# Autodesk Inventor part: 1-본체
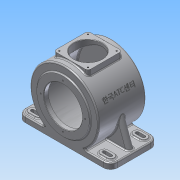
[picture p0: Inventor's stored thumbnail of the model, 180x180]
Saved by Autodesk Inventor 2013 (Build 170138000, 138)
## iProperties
Created: 2015-06
Part Number: 1-본체
Material: 알루미늄 6061
Document SubType Name: Modeling
Designer: ST5
Density: 2.71 g/cm^3
Mass: 3341.58 g
Surface Area: 2297.32 cm^2
Volume: 1233.06 cm^3
Author: ST5
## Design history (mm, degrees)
sketch "스케치1"
  geometry: L1 (-115, 59)-(115, 59); L2 (115, 59)-(115, -59); L3 (115, -59)-(-115, -59); L4 (-115, -59)-(-115, 59); 3 further points
  constraints: 8 end point, 2 midpoint, 2 parallel, 1 horizontal, 1 horizontal alignment, 1 perpendicular, 1 vertical alignment
  dimensions: "d0" = 230 distance of L1.start L1.end; "d2" = 118 distance of L3.end L1.start
extrude "돌출1" new body sketch "스케치1" distance "d3" = 14; taper "d4" = 0 deg
node "작업 평면1"
sketch "스케치2"
  geometry: L1 (115, 0)-(-115, 0) reference; C1 r 85 at (0, 85); 2 further points
  constraints: 1 centre point, 1 midpoint, 1 vertical alignment
  dimensions: "d6" = 170 diameter of C1; "d8" = 85 distance of point (0, 0) C1.centre
extrude "돌출2" join sketch "스케치2" stored distance "d9" = 118; taper "d10" = 0 deg
node "작업 평면2"
sketch "스케치3"
  geometry: L1 (-42.5, 42.5)-(42.5, 42.5); L2 (42.5, 42.5)-(42.5, -42.5); L3 (42.5, -42.5)-(-42.5, -42.5); L4 (-42.5, -42.5)-(-42.5, 42.5); 3 further points
  constraints: 8 end point, 2 midpoint, 2 parallel, 2 perpendicular, 1 horizontal, 1 horizontal alignment, 1 vertical alignment
  dimensions: "d12" = 85 distance of L1.start L1.end
extrude "돌출3" join sketch "스케치3" stored distance "d14" = 118; taper "d15" = 0 deg
node "작업 평면3"
sketch "스케치4"
  geometry: L1 (0, 14)-(68.267, 14) reference; L2 (0, 0)-(0, 14) reference; L3 (230, 0)-(0, 0) reference; L4 (230, 0)-(230, 14) reference; L5 (161.733, 14)-(230, 14) reference; L6 (6, 14)-(30.13, 80.297); L7 (0, 14)-(68.267, 14) reference; A1 r 85 centre (115, 85) between (161.733, 14) and (68.267, 14) reference; 1 further point
  constraints: 2 end point, 1 point on circle, 1 point on line
  dimensions: "d16" = 6 distance from line of L2 L6.start; "d17" = 110 deg angle of L1 L6
extrude "돌출4" join sketch "스케치4" stored distance "d18" = 15; taper "d19" = 0 deg
node "작업 평면4"
sketch "스케치5"
  geometry: C1 r 65 at (115, 85); A1 r 85 centre (115, 85) between (161.733, 14) and (68.267, 14) reference; 1 further point
  constraints: 1 centre point, 1 coincident
  dimensions: "d21" = 130 diameter of C1
extrude "돌출5" join sketch "스케치5" distance "d23" = 3; taper "d24" = 0 deg
sketch "스케치6"
  geometry: C1 r 65 at (0, 0) reference; C2 r 47.5 at (0, 0); 1 further point
  constraints: 1 centre point, 1 coincident
  dimensions: "d25" = 95 diameter of C2
extrude "돌출6" cut sketch "스케치6" distance "d27" = 11; taper "d28" = 0 deg
sketch "스케치7"
  geometry: C1 r 47.5 at (0, 0) reference; C2 r 77 at (0, 0); 1 further point
  constraints: 1 centre point, 1 coincident
  dimensions: "d29" = 154 diameter of C2
extrude "돌출7" cut sketch "스케치7" distance "d31" = 102; taper "d32" = 0 deg
sketch "스케치8"
  geometry: C1 r 77 at (0, 0) reference; C2 r 31 at (0, 0); 1 further point
  constraints: 1 centre point, 1 coincident
  dimensions: "d33" = 62 diameter of C2
extrude "돌출8" join sketch "스케치8" distance "d35" = 3.5; taper "d36" = -25 deg
sketch "스케치9"
  geometry: C1 r 65 at (115, -85); A1 r 85 centre (115, -85) between (68.267, -14) and (161.733, -14) reference; 1 further point
  constraints: 1 centre point, 1 coincident
  dimensions: "d37" = 130 diameter of C1
extrude "돌출9" join sketch "스케치9" distance "d39" = 13; taper "d40" = 0 deg
sketch "스케치10"
  geometry: C1 r 29.368 at (0, 0) reference; C2 r 23.5 at (0, 0); 1 further point
  constraints: 1 centre point, 1 coincident
  dimensions: "d41" = 47 diameter of C2
extrude "돌출10" cut sketch "스케치10" distance "d43" = 14; taper "d44" = 0 deg
sketch "스케치11"
  geometry: C1 r 23.5 at (0, 0) reference; C2 r 15 at (0, 0); 1 further point
  constraints: 1 centre point, 1 coincident
  dimensions: "d45" = 30 diameter of C2
extrude "돌출11" cut sketch "스케치11" distance "d47" = 3; taper "d48" = 0 deg
fillet "모깎기1" dims "d49" = 0.3
fillet "모깎기2" dims "d50" = 3
chamfer "모따기1" distance "d51" = 1; stored, may be unused: second distance "d52" = 2, angle "d53" = 45 deg
fillet "모깎기4" dims "d55" = 3
fillet "모깎기5" dims "d56" = 3
fillet "모깎기6" dims "d57" = 3
fillet "모깎기7" dims "d58" = 7.5
fillet "모깎기8" dims "d59" = 7
fillet "모깎기9" dims "d60" = 18
sketch "스케치12"
  geometry: C1 r 65 at (0, 0) reference; 2 further points
  constraints: 1 vertical alignment
  dimensions: "d61" = 55 distance of C1.centre point (0, 55)
hole "구멍1" sketch "스케치12" at (0, 55) diameter "d62" = 3.459; stored, may be unused: countersink angle "d66" = 90 deg, drill point angle "d68" = 118 deg; dims "d63" = 20, "d64" = 4, "d65" = 2, "d67" = 20
sketch "스케치13"
  geometry: A1 r 7 centre (-35.5, 35.5) between (-35.5, 42.5) and (-42.5, 35.5) reference; A2 r 7 centre (-35.5, -35.5) between (-42.5, -35.5) and (-35.5, -42.5) reference; A3 r 7 centre (35.5, -35.5) between (35.5, -42.5) and (42.5, -35.5) reference; A4 r 7 centre (35.5, 35.5) between (42.5, 35.5) and (35.5, 42.5) reference; 5 further points
  constraints: 4 coincident
hole "구멍2" sketch "스케치13" at (-35.5, 35.5), (35.5, 35.5), (35.5, -35.5), (-35.5, -35.5) diameter "d72" = 3.459; stored, may be unused: countersink angle "d76" = 90 deg, drill point angle "d78" = 118 deg; dims "d73" = 10, "d74" = 4, "d75" = 2, "d77" = 13
sketch "스케치14"
  geometry: C1 r 35 at (0, 0); 1 further point
  constraints: 1 centre point, 1 coincident
  dimensions: "d79" = 70 diameter of C1
extrude "돌출12" cut sketch "스케치14" distance "d81" = 20; taper "d82" = 0 deg
chamfer "모따기2" distance "d83" = 1; stored, may be unused: second distance "d84" = 2, angle "d85" = 45 deg
fillet "모깎기10" dims "d86" = 3
fillet "모깎기11" dims "d87" = 3
node "작업 평면5"
sketch "스케치15"
  geometry: L1 (0, 85)-(77.036, 120.923); C1 r 12 at (0, 85) reference; A1 r 85 centre (0, 85) between (46.733, 14) and (-46.733, 14) reference; 3 further points
  constraints: 2 end point, 2 horizontal alignment, 1 point on circle, 1 other
  dimensions: "d91" = 25 deg dimension on L1.start L1.end point (74, 85)
  node "투영된 루프2"
fillet "모깎기14" dims "d94" = 3
fillet "모깎기15" dims "d95" = 3
fillet "모깎기16" dims "d96" = 2.7
node "작업 평면7"
sketch "스케치17"
  geometry: L1 (112.3, 41)-(112.3, -41) reference; L2 (81, 50)-(97, 50); L3 (97, 32)-(81, 32); L4 (97, 59)-(55.845, 59) reference; L5 (115, -41)-(115, 41) reference; A1 r 9 centre (97, 41) between (97, 32) and (97, 50); A2 r 9 centre (81, 41) between (81, 50) and (81, 32); 1 further point
  constraints: 4 end point, 4 point on circle, 4 tangent, 2 centre point, 1 parallel, 1 perpendicular
  dimensions: "d97" = 9 radius of A2; "d99" = 16 distance of A2.centre A1.centre; "d100" = 18 distance from line of L4 A1.centre; "d101" = 18 distance from line of L5 A1.centre
extrude "돌출13" join sketch "스케치17" distance "d102" = 3; taper "d103" = 0 deg
sketch "스케치18"
  geometry: L1 (81, 45)-(97, 45); L2 (81, 37)-(97, 37); A1 r 9 centre (81, 41) between (81, 50) and (81, 32) reference; A2 r 9 centre (97, 41) between (97, 32) and (97, 50) reference; A3 r 4 centre (81, 41) between (81, 45) and (81, 37); A4 r 4 centre (97, 41) between (97, 37) and (97, 45); 1 further point
  constraints: 4 end point, 4 point on circle, 4 tangent, 2 centre point, 2 coincident, 1 equal radius
  dimensions: "d104" = 8 diameter of A3
extrude "돌출14" cut sketch "스케치18" stored distance "d106" = 3; taper "d107" = 0 deg
node "작업 평면8"
node "작업 평면9"
fillet "모깎기17" dims "d108" = 18
fillet "모깎기18" dims "d109" = 2.5
fillet "모깎기19" dims "d110" = 2.5
sketch "스케치19"
  geometry: L1 (81, 45)-(97, 45) reference; L2 (97, 37)-(81, 37) reference; L3 (81, 45)-(97, 45); L4 (81, 37)-(97, 37); A1 r 4 centre (81, 41) between (81, 45) and (81, 37) reference; A2 r 4 centre (97, 41) between (97, 37) and (97, 45) reference; A3 r 4 centre (97, 41) between (97, 37) and (97, 45); A4 r 4 centre (81, 41) between (81, 45) and (81, 37); 1 further point
  constraints: 8 tangent, 4 end point, 4 point on circle, 2 centre point, 2 coincident, 2 collinear, 1 concentric, 1 point on line
extrude "돌출15" cut sketch "스케치19" stored distance "d111" = 3; taper "d112" = 0 deg
node "작업 평면10"
fillet "모깎기20" dims "d114" = 3
sketch "스케치20"
  geometry: L1 (0, 85)-(77.036, 120.923); C1 r 12 at (0, 85) reference; A1 r 85 centre (0, 85) between (53.953, 19.318) and (-53.953, 19.318) reference; 2 further points
  constraints: 2 end point, 2 horizontal alignment, 1 point on circle, 1 other
  dimensions: "d115" = 25 deg dimension on C1.centre point (62, 85) L1.end
  node "투영된 루프4"
node "작업 평면11"
sketch "스케치21"
  geometry: L1 (-35.5, 47.366)-(35.5, 47.366) reference; L2 (56, -36.727)-(56, 85) reference; L3 (59, -80.996)-(59, -42.262) reference; L4 (56, 85)-(56, 85) reference; 4 further points
  constraints: 1 horizontal alignment, 1 midpoint, 1 point on line, 1 vertical alignment, 3 other
feature "엠보싱2" sketch "스케치21" dims "d116" = 0.5, "d117" = 0
node "작업 평면12"
sketch "스케치22"
  geometry: L1 (85.201, 14)-(144.799, 14); C1 r 12 at (115, 85) reference; A1 r 77 centre (115, 85) between (144.799, 14) and (85.201, 14) reference; A2 r 77 centre (115, 85) between (85.201, 14) and (144.799, 14); 1 further point
  constraints: 2 end point, 2 point on circle, 1 centre point, 1 coincident, 1 concentric, 1 horizontal
extrude "돌출16" cut sketch "스케치22" stored distance "d119" = 102; taper "d120" = 0 deg
fillet "모깎기21" dims "d121" = 3
node "솔리드1"
mirror "대칭1"
pattern_circular "원형 패턴1" dims angle "d70" = 360 deg
mirror "대칭2"
mirror "대칭3"
mirror "대칭4"
mirror "대칭5"
mirror "대칭6"
node "투영된 루프1"
node "투영된 루프3"
node "투영된 루프5"
node "투영된 루프6"
other parameters: "d5" = 0, "d11" = 173, "d20" = 0, "d90" = 0, "d113" = 0, "d118" = 0
